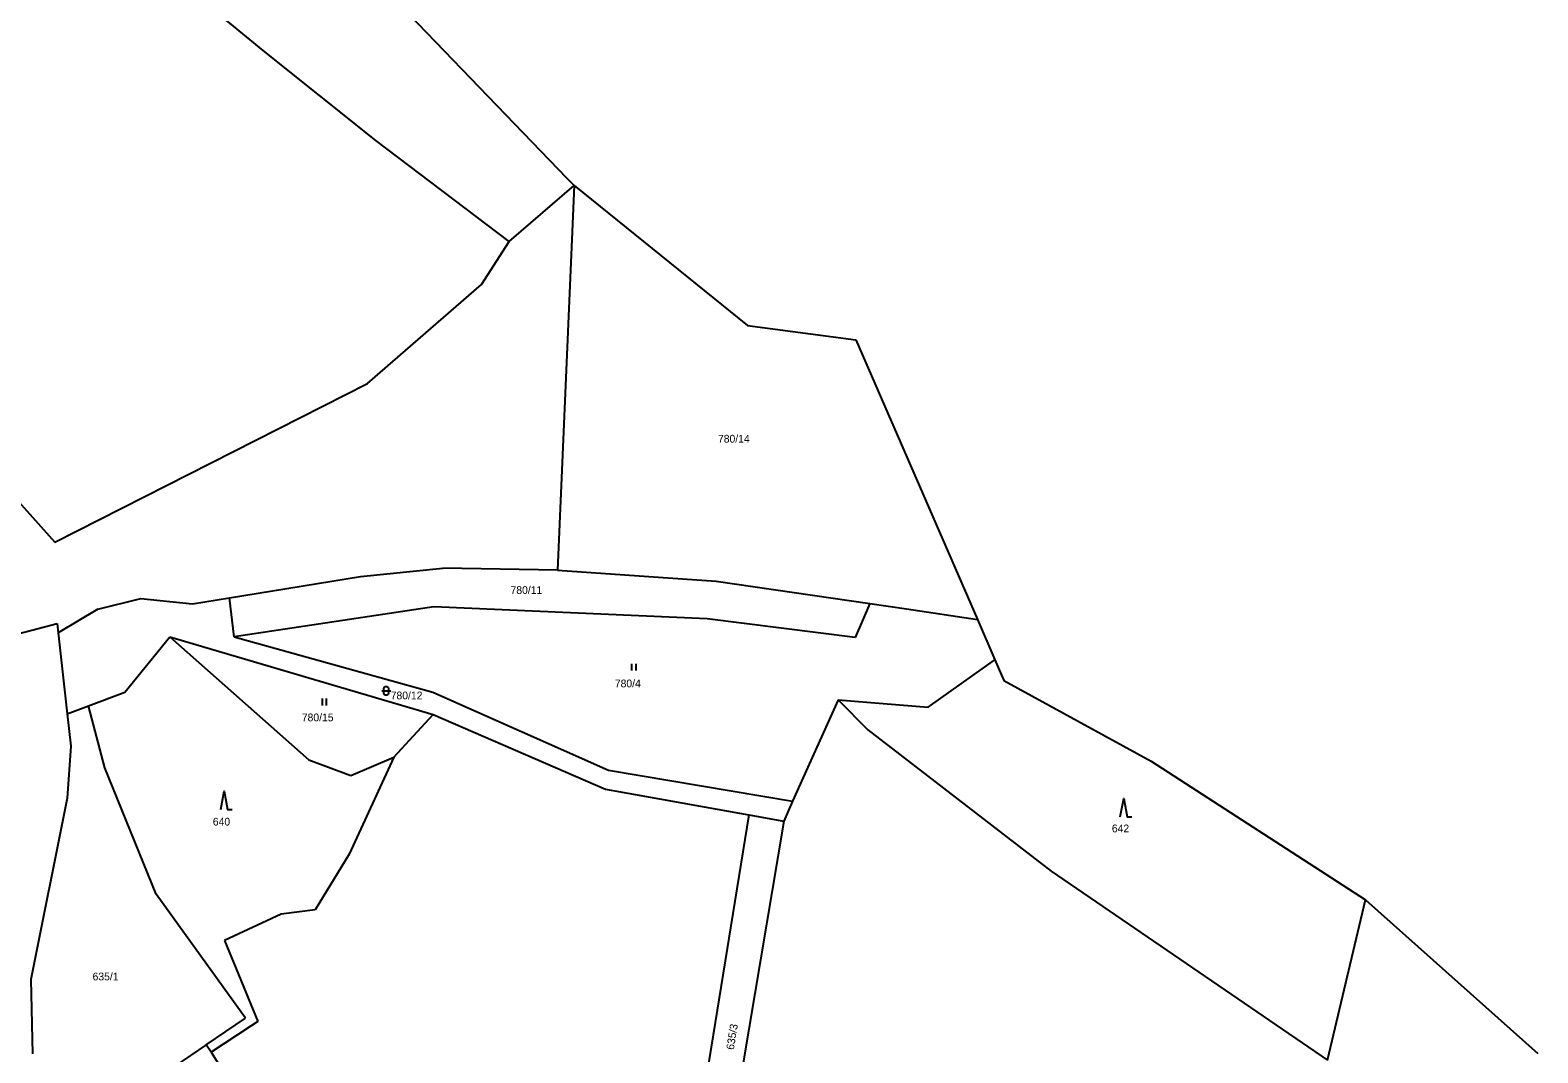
# Model space of a CAD drawing. Extents: x -801907 to -800293, y -1016964 to -1015684.
# Drawn here: x -800807.1 to -800476.8, y -1016132.8 to -1015908.8 of the extents above; entities that cross this region are included whole.
import ezdxf

# ---------------------------------------------------------------- set-up
doc = ezdxf.new("R2010")
doc.units = 0
for name, color, linetype in [('Default', 7, 'Continuous'), ('KN_HRANICE', 7, 'Continuous'), ('KN_KULTURY', 7, 'Continuous'), ('KN_PARCELY', 7, 'Continuous')]:
    doc.layers.add(name, color=color, linetype=linetype)

# ---------------------------------------------------------------- blocks, each defined once
blk = doc.blocks.new('306')
at = {"layer": 'Default'}
for p, q in [((-0.5, 1.5), (-0.5, 0)), ((0.5, 0), (0.5, 1.5))]:
    blk.add_line(p, q, dxfattribs=at)
blk = doc.blocks.new('308')
at = {"layer": 'Default'}
blk.add_lwpolyline([(-0.75, 0), (0, 4), (0.75, 0), (1.75, 0)], dxfattribs=at)
blk = doc.blocks.new('316')
at = {"layer": 'Default'}
for points in [[(-1, 1), (0.27, 1), (1, 1)], [(-0.5, 1.5), (-0.4, 1.79), (-0.15, 1.97), (0.16, 1.97), (0.41, 1.79), (0.51, 1.5), (0.51, 0.5), (0.41, 0.21), (0.16, 0.03), (-0.15, 0.03), (-0.4, 0.21), (-0.5, 0.5), (-0.5, 1.5)]]:
    blk.add_lwpolyline(points, dxfattribs=at)

msp = doc.modelspace()

# ---------------------------------------------------------------- linework, layer by layer
at = {"layer": 'KN_HRANICE'}
for p, q in [((-800730.51, -1015898.56), (-800689.48, -1015941.19)), ((-800756.01, -1015913.25), (-800769.79, -1015901.81)), ((-800731.31, -1015932.96), (-800756.01, -1015913.25)), ((-800702.15, -1015955.09), (-800731.31, -1015932.96)), ((-800702.15, -1015955.09), (-800687.91, -1015942.82)), ((-800687.91, -1015942.82), (-800691.57, -1016027.07)), ((-800689.48, -1015941.19), (-800687.91, -1015942.82)), ((-800687.91, -1015942.82), (-800649.96, -1015973.49)), ((-800708.23, -1015964.5), (-800702.15, -1015955.09)), ((-800733.15, -1015986.18), (-800708.23, -1015964.5)), ((-800649.96, -1015973.49), (-800626.22, -1015976.61)), ((-800626.22, -1015976.61), (-800599.58, -1016037.93)), ((-800801.68, -1016020.93), (-800733.15, -1015986.18)), ((-800826.83, -1015992.84), (-800801.68, -1016020.93)), ((-800763.42, -1016033.13), (-800734.7, -1016028.44)), ((-800734.7, -1016028.44), (-800716.7, -1016026.66)), ((-800691.57, -1016027.07), (-800716.7, -1016026.66)), ((-800691.57, -1016027.07), (-800656.81, -1016029.48)), ((-800656.81, -1016029.48), (-800623.14, -1016034.39)), ((-800792.26, -1016035.61), (-800800.93, -1016040.79)), ((-800792.26, -1016035.61), (-800782.84, -1016033.31)), ((-800782.84, -1016033.31), (-800771.53, -1016034.46)), ((-800771.53, -1016034.46), (-800763.42, -1016033.13)), ((-800762.37, -1016041.73), (-800763.42, -1016033.13)), ((-800718.61, -1016035.13), (-800762.37, -1016041.73)), ((-800658.78, -1016037.74), (-800718.61, -1016035.13)), ((-800623.14, -1016034.39), (-800626.32, -1016041.82)), ((-800623.14, -1016034.39), (-800615.13, -1016035.56)), ((-800615.13, -1016035.56), (-800599.58, -1016037.93)), ((-800812.57, -1016041.79), (-800801.16, -1016038.76)), ((-800801.16, -1016038.76), (-800800.93, -1016040.79)), ((-800626.32, -1016041.82), (-800658.78, -1016037.74)), ((-800599.58, -1016037.93), (-800595.76, -1016046.73)), ((-800800.93, -1016040.79), (-800798.96, -1016058.55)), ((-800786.31, -1016053.81), (-800776.47, -1016041.66)), ((-800776.47, -1016041.66), (-800746.03, -1016068.65)), ((-800776.47, -1016041.66), (-800718.78, -1016058.74)), ((-800762.37, -1016041.73), (-800718.83, -1016053.85)), ((-800610.33, -1016057.07), (-800595.76, -1016046.73)), ((-800595.76, -1016046.73), (-800593.79, -1016051.26)), ((-800593.79, -1016051.26), (-800561.5, -1016068.96)), ((-800794.32, -1016056.81), (-800786.31, -1016053.81)), ((-800718.83, -1016053.85), (-800680.37, -1016070.94)), ((-800630.08, -1016055.49), (-800640.04, -1016077.67)), ((-800630.08, -1016055.49), (-800610.33, -1016057.07)), ((-800630.08, -1016055.49), (-800623.6, -1016062.07)), ((-800798.96, -1016058.55), (-800794.32, -1016056.81)), ((-800798.96, -1016058.55), (-800798.15, -1016065.67)), ((-800790.73, -1016070.43), (-800794.32, -1016056.81)), ((-800727.37, -1016068.06), (-800718.78, -1016058.74)), ((-800718.78, -1016058.74), (-800681.02, -1016075.08)), ((-800623.6, -1016062.07), (-800583.45, -1016093.02)), ((-800798.15, -1016065.67), (-800798.97, -1016077.03)), ((-800746.03, -1016068.65), (-800736.79, -1016072.04)), ((-800727.37, -1016068.06), (-800737.18, -1016089.33)), ((-800736.79, -1016072.04), (-800727.37, -1016068.06)), ((-800561.5, -1016068.96), (-800514.57, -1016099.34)), ((-800779.49, -1016098.06), (-800790.73, -1016070.43)), ((-800680.37, -1016070.94), (-800640.04, -1016077.67)), ((-800681.02, -1016075.08), (-800649.62, -1016080.7)), ((-800798.97, -1016077.03), (-800806.9, -1016116.78)), ((-800640.04, -1016077.67), (-800642.01, -1016082.06)), ((-800649.62, -1016080.7), (-800658.77, -1016137)), ((-800642.01, -1016082.06), (-800650.89, -1016135.02)), ((-800649.62, -1016080.7), (-800642.01, -1016082.06)), ((-800737.18, -1016089.33), (-800744.66, -1016101.5)), ((-800583.45, -1016093.02), (-800522.87, -1016134.41)), ((-800759.86, -1016125.22), (-800779.49, -1016098.06)), ((-800744.66, -1016101.5), (-800752.05, -1016102.49)), ((-800522.87, -1016134.41), (-800514.57, -1016099.34)), ((-800514.57, -1016099.34), (-800476.81, -1016132.98)), ((-800752.05, -1016102.49), (-800764.51, -1016108.23)), ((-800764.51, -1016108.23), (-800757.19, -1016125.94)), ((-800806.9, -1016116.78), (-800806.54, -1016133.07)), ((-800768.52, -1016131.08), (-800759.86, -1016125.22)), ((-800758.66, -1016126.91), (-800767.44, -1016132.7)), ((-800757.19, -1016125.94), (-800758.66, -1016126.91)), ((-800768.52, -1016131.08), (-800778.84, -1016138.06)), ((-800767.44, -1016132.7), (-800768.52, -1016131.08)), ((-800767.44, -1016132.7), (-800746.19, -1016166.34))]:
    msp.add_line(p, q, dxfattribs=at)

# ---------------------------------------------------------------- block references
at = {"layer": 'KN_KULTURY'}
for name, p in [('306', (-800674.82, -1016049.08)), ('316', (-800729.06, -1016054.54)), ('306', (-800742.62, -1016056.72)), ('308', (-800764.58, -1016079.5)), ('308', (-800567.52, -1016081.11))]:
    msp.add_blockref(name, p, dxfattribs=at)

# ---------------------------------------------------------------- texts
at = {"layer": 'KN_PARCELY'}
for s, p in [('780/14', (-800656.4, -1015999.14)), ('780/11', (-800701.84, -1016032.3)), ('780/4', (-800678.99, -1016052.76)), ('780/12', (-800728.09, -1016055.39)), ('780/15', (-800747.56, -1016060.2)), ('640', (-800767.05, -1016083.04)), ('642', (-800570.12, -1016084.52)), ('635/1', (-800793.39, -1016116.96))]:
    msp.add_text(s, height=1.7, dxfattribs=at).set_placement(p)
msp.add_text('635/3', height=1.7, rotation=81.016, dxfattribs=at).set_placement((-800652.93, -1016132.26))

doc.saveas('drawing.dxf')
